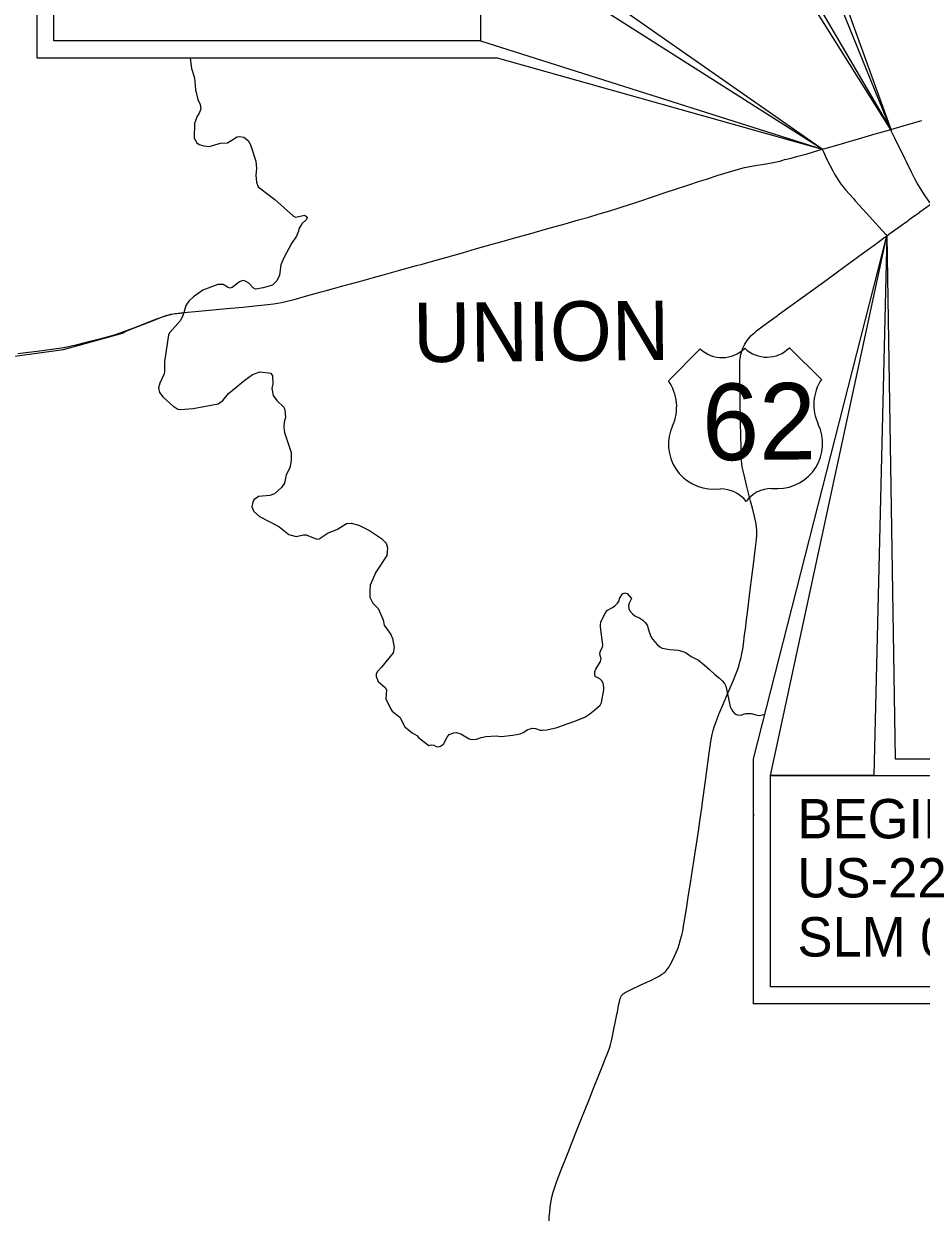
# Model space of a CAD drawing. Extents: x -12 to 164, y -741 to 24.
# Drawn here: x 5.301 to 8.492, y 14.264 to 18.513 of the extents above; entities that cross this region are included whole.
import ezdxf

# ---------------------------------------------------------------- set-up
doc = ezdxf.new("R2010")
doc.units = 0
for name, color, linetype in [('Default', 7, 'Continuous'), ('PM_P_Channelizing_Line', 7, 'Continuous'), ('PM_P_Crosswalk', 7, 'Continuous'), ('PM_P_Stop_Line', 7, 'Continuous'), ('PM_X_Channelizing_Line', 7, 'Continuous'), ('SH_Data', 7, 'Continuous'), ('SH_Text', 7, 'Continuous')]:
    doc.layers.add(name, color=color, linetype=linetype)

msp = doc.modelspace()

# ---------------------------------------------------------------- linework, layer by layer
at = {"layer": 'PM_P_Channelizing_Line'}
for points in [[(5.8926, 18.3927), (5.8923, 18.3914), (5.8977, 18.3544), (5.9077, 18.3222), (5.9115, 18.2795), (5.92, 18.2444), (5.9277, 18.2272), (5.9304, 18.2106), (5.9236, 18.1939), (5.9174, 18.1857), (5.9073, 18.1593), (5.9065, 18.1071), (5.9161, 18.0903), (5.924, 18.0844), (5.9413, 18.0795), (5.9596, 18.0775), (6.0007, 18.0895), (6.0255, 18.0909), (6.059, 18.1119), (6.0674, 18.1133), (6.0832, 18.1109), (6.0997, 18.0982), (6.1086, 18.0797), (6.1261, 18.0259), (6.1279, 17.9996), (6.1259, 17.9754), (6.128, 17.9509), (6.1348, 17.9337), (6.1937, 17.8893), (6.2596, 17.8293), (6.2675, 17.8266), (6.3005, 17.8335), (6.3084, 17.8263), (6.306, 17.8181), (6.2891, 17.8023), (6.2786, 17.7849), (6.278, 17.7765), (6.2706, 17.7591), (6.2523, 17.7332), (6.2257, 17.6818), (6.215, 17.6563), (6.2099, 17.6202), (6.201, 17.6003), (6.1854, 17.5845), (6.1518, 17.5754), (6.1252, 17.5702), (6.1166, 17.5754), (6.1007, 17.5919), (6.0849, 17.6006), (6.0758, 17.6005), (6.0677, 17.5966), (6.0414, 17.5766), (6.0336, 17.5744), (6.0257, 17.5774), (6.0093, 17.5867), (5.9913, 17.5869), (5.9377, 17.5669), (5.9043, 17.5434), (5.8875, 17.5282), (5.8772, 17.5118), (5.8695, 17.4867)], [(5.1797, 17.3207), (5.4419, 17.3559), (5.6519, 17.4137), (5.6697, 17.4237), (5.7583, 17.4583), (5.7937, 17.4721), (5.818, 17.4795), (5.8319, 17.4824), (5.8695, 17.4867)], [(5.8695, 17.4867), (5.8665, 17.4772), (5.8576, 17.4595), (5.8199, 17.4162), (5.8156, 17.4083), (5.8013, 17.3125), (5.801, 17.2773), (5.7995, 17.2694), (5.7841, 17.2367), (5.7802, 17.2194), (5.7838, 17.2031), (5.7965, 17.1862), (5.831, 17.1558), (5.8488, 17.144), (5.8576, 17.1425), (5.9025, 17.1457), (5.9923, 17.1622), (6.0086, 17.1749), (6.0291, 17.199), (6.0881, 17.2484), (6.114, 17.2669), (6.1397, 17.2759), (6.1797, 17.2715), (6.1858, 17.2628), (6.186, 17.2339), (6.1834, 17.2169), (6.188, 17.1919), (6.2007, 17.1741), (6.2251, 17.1508), (6.2293, 17.1417), (6.2311, 17.1147), (6.2266, 17.0971), (6.2255, 17.0792), (6.2278, 17.0613), (6.2518, 16.9894), (6.2514, 16.9617), (6.2472, 16.9347), (6.2339, 16.9098), (6.2282, 16.8812), (6.217, 16.8648), (6.1921, 16.8426), (6.1754, 16.8365), (6.1349, 16.8327), (6.1187, 16.8215), (6.115, 16.8137), (6.1123, 16.7967), (6.1193, 16.7804), (6.1393, 16.7627), (6.2082, 16.7269), (6.2434, 16.6986), (6.2698, 16.6907), (6.2959, 16.6972), (6.3044, 16.697), (6.3423, 16.6816), (6.3517, 16.6826), (6.3836, 16.7046), (6.4002, 16.7098), (6.4165, 16.7171), (6.4484, 16.7375), (6.465, 16.7379), (6.4928, 16.7316), (6.53, 16.7125), (6.5731, 16.684), (6.5893, 16.6672), (6.5941, 16.6509), (6.5919, 16.6232), (6.5524, 16.5642), (6.5321, 16.5184), (6.5314, 16.4963), (6.5316, 16.4759), (6.5415, 16.4542), (6.5607, 16.4356), (6.5782, 16.3945), (6.5829, 16.3763), (6.6064, 16.343), (6.6117, 16.3286), (6.6174, 16.2966), (6.6142, 16.2778), (6.5734, 16.2268), (6.557, 16.2101), (6.5542, 16.202), (6.5539, 16.1938), (6.5611, 16.176), (6.5862, 16.1546), (6.5903, 16.1465), (6.588, 16.1135), (6.6046, 16.0797), (6.6109, 16.0703), (6.6382, 16.0489), (6.656, 16.0141), (6.6815, 15.9931), (6.6987, 15.9833), (6.7056, 15.9755), (6.741, 15.9475), (6.7492, 15.95), (6.7586, 15.949), (6.767, 15.9446), (6.7749, 15.9439), (6.7827, 15.9461), (6.7928, 15.953), (6.806, 15.9777), (6.8139, 15.9871), (6.8299, 15.9936), (6.8381, 15.9945), (6.8472, 15.992), (6.8553, 15.9895), (6.8847, 15.9721), (6.8932, 15.9696), (6.9111, 15.9711), (6.9274, 15.977), (6.9441, 15.9798), (6.9811, 15.9819), (6.9986, 15.9802), (7.0401, 15.9845), (7.0661, 15.9898), (7.0765, 15.9944), (7.0928, 16.005), (7.1101, 16.0094), (7.1201, 16.0081), (7.137, 16.0024), (7.1452, 16.002), (7.1612, 16.0039), (7.1979, 16.0116), (7.2293, 16.024), (7.2604, 16.034), (7.2692, 16.0387), (7.2962, 16.0492), (7.3132, 16.0602), (7.3318, 16.0745), (7.3503, 16.0917), (7.3557, 16.1011), (7.363, 16.1462), (7.3634, 16.155), (7.3609, 16.1682), (7.3578, 16.1764), (7.3493, 16.1849), (7.3327, 16.1934), (7.3309, 16.2012), (7.3319, 16.2113), (7.3347, 16.2197), (7.3511, 16.2466), (7.3543, 16.256), (7.3496, 16.273), (7.35, 16.2815), (7.3582, 16.2984), (7.3601, 16.3065), (7.3518, 16.3689), (7.3515, 16.3771), (7.3531, 16.3865), (7.3695, 16.421), (7.3771, 16.4294), (7.3944, 16.4391), (7.4028, 16.445), (7.412, 16.4537), (7.4186, 16.4622), (7.4192, 16.4703), (7.43, 16.4869), (7.4379, 16.4903), (7.446, 16.4884), (7.4622, 16.4701), (7.4527, 16.4521), (7.4511, 16.4436), (7.4524, 16.4348), (7.4561, 16.4266), (7.4655, 16.4166), (7.4739, 16.4096), (7.4918, 16.4011), (7.5024, 16.3936), (7.5118, 16.3838), (7.519, 16.3734), (7.5212, 16.3625), (7.5302, 16.3361), (7.5361, 16.326), (7.5533, 16.3068), (7.5624, 16.2993), (7.5708, 16.2942), (7.5981, 16.2898), (7.6285, 16.2865), (7.6476, 16.2815), (7.6567, 16.277), (7.6746, 16.2641), (7.7002, 16.2509), (7.7206, 16.2354), (7.7397, 16.2188), (7.7578, 16.2002), (7.7753, 16.187), (7.7847, 16.1775), (7.7922, 16.1687), (7.7975, 16.159), (7.8074, 16.1154), (7.8124, 16.0859), (7.818, 16.0768), (7.822, 16.0686), (7.8292, 16.0607), (7.838, 16.0573), (7.8521, 16.0563), (7.86, 16.06), (7.8681, 16.0619), (7.8876, 16.0621), (7.9092, 16.0555), (7.9173, 16.0542), (7.9361, 16.0597)], [(7.8956, 15.7231), (7.895, 15.7212), (7.894, 15.7124), (7.8956, 15.6977)]]:
    msp.add_lwpolyline(points, dxfattribs=at)
at = {"layer": 'PM_P_Crosswalk'}
msp.add_line((7.7702, 17.9755), (7.8502, 17.9993), dxfattribs=at)
for points in [[(7.9899, 18.0254), (7.9998, 18.0292), (8.0057, 18.031), (8.0126, 18.0327), (8.0292, 18.0365), (8.0492, 18.0415), (8.0864, 18.0519), (8.1401, 18.0676), (8.1438, 18.0687), (8.1506, 18.0706), (8.2123, 18.0885), (8.2357, 18.0952), (8.2395, 18.0963), (8.2488, 18.099), (8.2692, 18.1047), (8.3285, 18.122), (8.3805, 18.137), (8.3837, 18.1379), (8.4397, 18.1541), (8.4866, 18.1676), (8.4948, 18.1702)], [(8.5273, 17.8735), (8.5233, 17.879), (8.5038, 17.906), (8.4952, 17.9188), (8.4855, 17.9339), (8.4777, 17.9471), (8.469, 17.9629), (8.4574, 17.9857), (8.4383, 18.0248), (8.4345, 18.0324), (8.3982, 18.1068), (8.3923, 18.1191), (8.3867, 18.1311), (8.3849, 18.1348), (8.3837, 18.1379)], [(8.1401, 18.0676), (8.1417, 18.0639), (8.1433, 18.0605), (8.1568, 18.0319), (8.1681, 18.0089), (8.1775, 17.9907), (8.1836, 17.9794), (8.1916, 17.9663), (8.2, 17.9534), (8.2074, 17.943), (8.2152, 17.9329), (8.2234, 17.923), (8.2508, 17.8921), (8.2573, 17.8849), (8.3091, 17.8276), (8.3418, 17.7914), (8.3658, 17.7646), (8.37, 17.76)], [(7.8502, 17.9993), (7.8634, 18.0023), (7.8961, 18.0087), (7.9393, 18.0159), (7.9597, 18.0196), (7.9899, 18.0254)], [(5.2791, 17.3411), (5.3173, 17.3464), (5.3478, 17.3504), (5.4343, 17.3623), (5.4546, 17.3657), (5.4697, 17.3688), (5.4872, 17.373), (5.542, 17.3868), (5.5793, 17.3963), (5.6066, 17.4036), (5.6264, 17.4092), (5.6435, 17.4148), (5.6604, 17.4209), (5.6697, 17.4245), (5.7011, 17.4367), (5.761, 17.4599), (5.7946, 17.4725), (5.8068, 17.4766), (5.8166, 17.4795), (5.82, 17.4803), (5.824, 17.4813), (5.8315, 17.4827), (5.8391, 17.4838), (5.8595, 17.4861), (5.8698, 17.4871), (5.9234, 17.4922), (5.9848, 17.4978), (6.0231, 17.5016), (6.0793, 17.5068), (6.1228, 17.5108), (6.1688, 17.5154), (6.1892, 17.5178), (6.2045, 17.5201), (6.2171, 17.5225), (6.2321, 17.5261), (6.2619, 17.5342), (6.3114, 17.5476), (6.3585, 17.5604), (6.372, 17.5641), (6.4402, 17.5829), (6.4947, 17.5977), (6.5442, 17.6113), (6.5838, 17.6222), (6.6332, 17.6362), (6.6975, 17.6542), (6.7173, 17.6596), (6.7544, 17.6701), (6.8013, 17.6834), (6.8606, 17.7001), (6.9076, 17.7134), (6.9669, 17.7301), (7.0014, 17.74), (7.0336, 17.7489), (7.073, 17.76), (7.0954, 17.7663), (7.1646, 17.7857), (7.2264, 17.8029), (7.2733, 17.8163), (7.3104, 17.8267), (7.3474, 17.8376), (7.3769, 17.8466), (7.4037, 17.8553), (7.4282, 17.8631), (7.4697, 17.8766), (7.4991, 17.8859), (7.5332, 17.8973), (7.5818, 17.9136), (7.6623, 17.9401), (7.7038, 17.9537), (7.7282, 17.9617), (7.7702, 17.9755)], [(8.487, 17.8447), (8.5273, 17.8735), (8.5324, 17.8773), (8.5863, 17.9162), (8.6234, 17.9431)], [(8.4254, 17.8003), (8.4286, 17.8027), (8.4441, 17.8138)], [(8.4441, 17.8138), (8.4485, 17.817), (8.4593, 17.8248), (8.4647, 17.8287), (8.4868, 17.8445), (8.487, 17.8447)], [(8.3633, 17.7551), (8.37, 17.76), (8.381, 17.7679), (8.4254, 17.8003)], [(7.9837, 17.4789), (7.9881, 17.4825), (8.0266, 17.51), (8.0723, 17.5431), (8.1572, 17.605), (8.2214, 17.6518), (8.2483, 17.6715), (8.2835, 17.6971), (8.325, 17.7273), (8.3633, 17.7551)], [(7.8475, 17.2242), (7.8475, 17.2265), (7.8471, 17.2598), (7.8466, 17.2958), (7.8466, 17.3086), (7.8471, 17.3162), (7.848, 17.3238), (7.8493, 17.3314), (7.851, 17.3389), (7.853, 17.3463), (7.8554, 17.3535), (7.8581, 17.3607), (7.8613, 17.3677), (7.8648, 17.3745), (7.8687, 17.3811), (7.8729, 17.3875), (7.8775, 17.3936), (7.8824, 17.3995), (7.8876, 17.4052), (7.893, 17.4105), (7.8987, 17.4157), (7.9066, 17.4222), (7.9209, 17.4331), (7.9479, 17.4528), (7.9798, 17.4758)], [(7.9798, 17.4758), (7.9816, 17.4772), (7.9837, 17.4789)], [(7.8641, 16.342), (7.8667, 16.3621), (7.8706, 16.3952), (7.875, 16.4309), (7.8827, 16.4921), (7.8908, 16.5558), (7.8956, 16.5916), (7.902, 16.642), (7.9061, 16.6807), (7.9074, 16.6961), (7.9078, 16.7064), (7.9076, 16.7141), (7.9075, 16.7146), (7.9067, 16.7244), (7.9053, 16.7346), (7.9029, 16.7473), (7.8994, 16.7623), (7.8918, 16.7922), (7.8854, 16.817), (7.8719, 16.8693), (7.8644, 16.8991), (7.8586, 16.9241), (7.8555, 16.9392), (7.8539, 16.9493), (7.8529, 16.9595), (7.8524, 16.9697), (7.8518, 16.9902), (7.8515, 17.0159), (7.851, 17.0416), (7.8507, 17.057), (7.85, 17.0878), (7.8491, 17.1237), (7.8487, 17.152), (7.8485, 17.1751), (7.8481, 17.1982), (7.8475, 17.2242)], [(7.7246, 15.8225), (7.7259, 15.8318), (7.7378, 15.9209), (7.7426, 15.9539), (7.7453, 15.9691), (7.749, 15.9866), (7.7527, 16.0016), (7.7562, 16.0139), (7.7601, 16.0261), (7.7663, 16.043), (7.7738, 16.0621), (7.7889, 16.0975), (7.8038, 16.1319), (7.8093, 16.1446), (7.8244, 16.1801), (7.8331, 16.2015), (7.8384, 16.216), (7.8432, 16.2307), (7.8475, 16.2455), (7.8513, 16.2605), (7.8545, 16.2756), (7.8573, 16.2908), (7.8598, 16.3086), (7.8641, 16.342)], [(7.6471, 15.3055), (7.6472, 15.3061), (7.6569, 15.367), (7.6651, 15.4177), (7.6714, 15.4583), (7.6792, 15.5064), (7.6851, 15.5445), (7.6887, 15.5673), (7.6933, 15.5978), (7.6998, 15.6436), (7.705, 15.6792), (7.7127, 15.7351), (7.7132, 15.7389), (7.7246, 15.8225)], [(7.3652, 14.8247), (7.378, 14.8572), (7.3832, 14.8717), (7.3871, 14.884), (7.3898, 14.894), (7.3932, 14.909), (7.3995, 14.9392), (7.4041, 14.9618), (7.41, 14.9921), (7.4115, 15), (7.4162, 15.0249), (7.4188, 15.0374), (7.4207, 15.0449), (7.4223, 15.0497), (7.4244, 15.0543), (7.4256, 15.0565), (7.4269, 15.0586), (7.4283, 15.0608), (7.4299, 15.0626), (7.4315, 15.0642), (7.4331, 15.0658), (7.4356, 15.0677), (7.4398, 15.0705), (7.4465, 15.074), (7.4581, 15.0795), (7.4636, 15.0821), (7.4923, 15.0956), (7.493, 15.0959), (7.5162, 15.1065), (7.5187, 15.1076), (7.535, 15.1152), (7.544, 15.1196), (7.5511, 15.1233), (7.5602, 15.1282), (7.5667, 15.1323), (7.5732, 15.1366), (7.5773, 15.1397), (7.5812, 15.1432), (7.5848, 15.1469), (7.5881, 15.1509), (7.5912, 15.1551), (7.5953, 15.1616), (7.5991, 15.1684), (7.6096, 15.189), (7.6197, 15.2098), (7.6223, 15.2156), (7.6239, 15.2193), (7.6275, 15.2289), (7.6316, 15.2411), (7.6367, 15.2584), (7.6405, 15.2733), (7.6439, 15.2884), (7.6471, 15.3055)], [(7.1688, 14.2586), (7.1696, 14.274), (7.1709, 14.2893), (7.1729, 14.3071), (7.1752, 14.3224), (7.1775, 14.335), (7.1803, 14.3475), (7.1835, 14.3599), (7.1878, 14.3746), (7.1936, 14.3916), (7.1997, 14.4085), (7.2119, 14.4396), (7.2366, 14.5016), (7.2632, 14.5685), (7.2822, 14.6162), (7.3127, 14.6925), (7.326, 14.7259), (7.3507, 14.7879), (7.3648, 14.8237), (7.3652, 14.8247)]]:
    msp.add_lwpolyline(points, dxfattribs=at)
at = {"layer": 'PM_P_Stop_Line'}
for p, q in [((7.7055, 17.3588), (7.593, 17.2443)), ((8.1379, 17.2494), (8.0233, 17.3618)), ((7.7556, 16.8598), (7.7783, 16.8601)), ((7.9599, 16.8618), (7.9826, 16.862))]:
    msp.add_line(p, q, dxfattribs=at)
for centre, radius, start, end in [((7.7842, 17.4406), 0.1135, 226.1115, 314.9656), ((7.9431, 17.4421), 0.1135, 226.1115, 314.9656), ((7.4637, 17.1519), 0.1589, 335.0857, 35.5395), ((8.2689, 17.1595), 0.1589, 145.5376, 205.9914), ((7.7523, 17.0187), 0.1589, 155.3705, 271.1768), ((7.9829, 17.0209), 0.1589, 269.9003, 25.7066), ((7.7793, 16.7466), 0.1135, 37.4084, 90.5385), ((7.961, 16.7483), 0.1135, 90.5385, 143.6686)]:
    msp.add_arc(centre, radius, start, end, dxfattribs=at)
at = {"layer": 'SH_Data'}
for points in [[(7.0366, 20.4387), (8.3853, 18.1356), (7.4488, 20.4387)], [(6.9246, 18.4527), (5.4075, 18.4527), (5.4075, 19.2041), (6.9246, 19.2041)], [(6.9246, 18.4527), (8.1401, 18.0676), (6.9246, 18.8405)], [(7.9556, 15.8411), (8.37, 17.76), (8.3231, 15.8411)], [(7.9556, 15.8411), (9.4727, 15.8411), (9.4727, 15.0897), (7.9556, 15.0897)]]:
    msp.add_lwpolyline(points, close=True, dxfattribs=at)
at = {"layer": 'SH_Text'}
for p, q in [((8.3853, 18.1356), (6.9766, 20.3787)), ((7.5771, 20.3787), (8.3853, 18.1356)), ((5.3475, 19.2641), (5.3475, 18.3927)), ((8.1401, 18.0676), (6.9846, 18.8746)), ((5.3475, 18.3927), (6.9846, 18.3927)), ((6.9846, 18.3927), (8.1401, 18.0676)), ((7.8956, 15.9011), (8.37, 17.76)), ((8.37, 17.76), (8.3995, 15.9011)), ((7.8956, 15.0297), (7.8956, 15.9011)), ((8.3995, 15.9011), (9.5327, 15.9011)), ((9.5327, 15.0297), (7.8956, 15.0297))]:
    msp.add_line(p, q, dxfattribs=at)

# ---------------------------------------------------------------- texts
at = {"layer": 'Default'}
for s, p in [('BEGIN LOC 3', (8.0519, 15.6179)), ('US-22', (8.0519, 15.4079)), ('SLM 0.00', (8.0519, 15.1979))]:
    msp.add_text(s, height=0.14, dxfattribs=at).set_placement(p)
at = {"layer": 'PM_P_Stop_Line'}
msp.add_text('62', height=0.27243, rotation=0.5385, dxfattribs=at).set_placement((7.7139, 16.9616))
at = {"layer": 'PM_X_Channelizing_Line'}
msp.add_text('UNION', height=0.21134, rotation=0.5386, dxfattribs=at).set_placement((6.6863, 17.3104))

doc.saveas('drawing.dxf')
